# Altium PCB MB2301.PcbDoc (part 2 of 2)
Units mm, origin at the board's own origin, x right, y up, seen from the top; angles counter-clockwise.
Board outline 43 x 51.45 mm, 4 copper layers (Top Layer, Internal 1, Internal 2, Bottom Layer), stack 1.565 mm thick; 103 components, 91 nets, 383 pads, 756 vias.
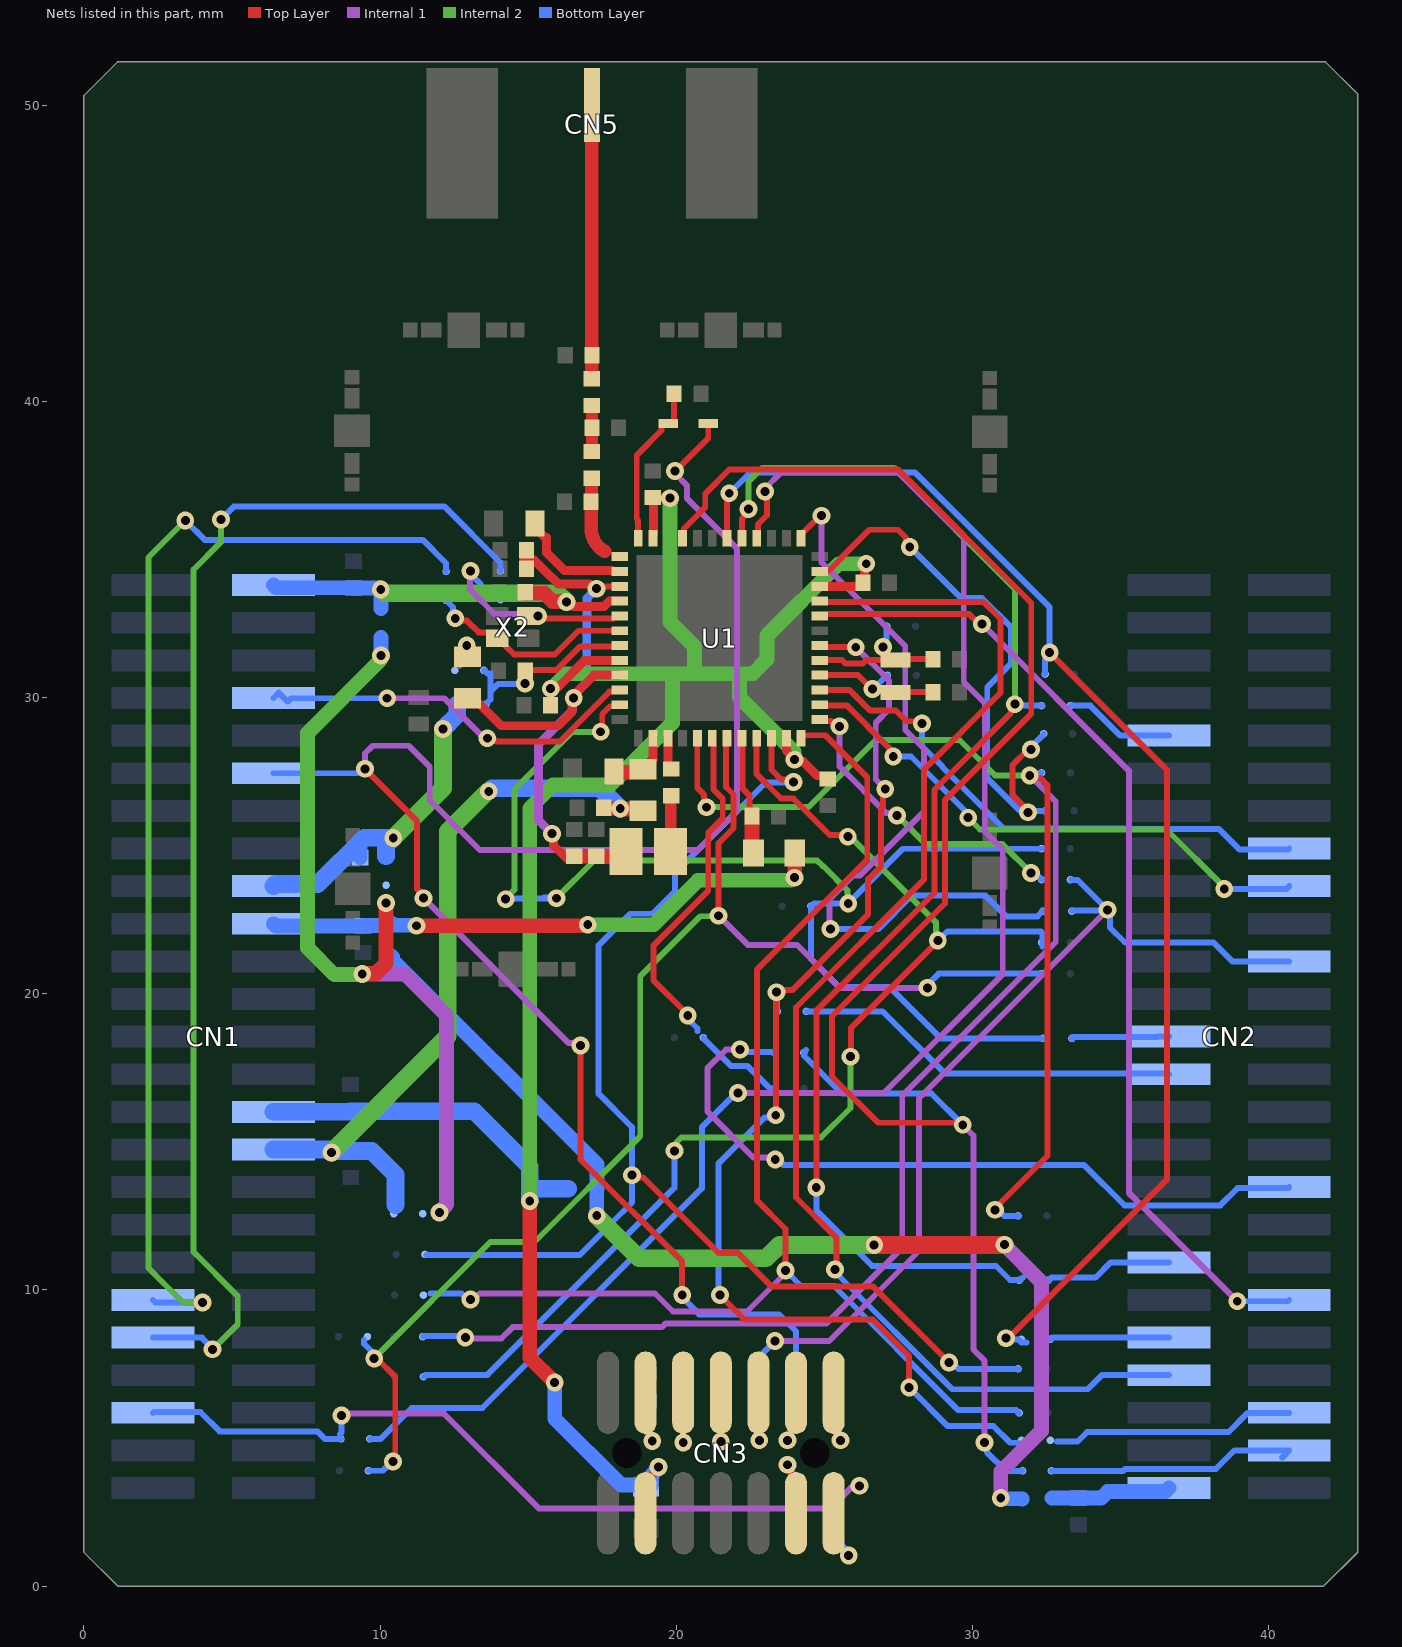
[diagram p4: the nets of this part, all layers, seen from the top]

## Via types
v1: diameter 0.6, hole 0.3, Top Layer to Bottom Layer, tented both sides, 756 vias

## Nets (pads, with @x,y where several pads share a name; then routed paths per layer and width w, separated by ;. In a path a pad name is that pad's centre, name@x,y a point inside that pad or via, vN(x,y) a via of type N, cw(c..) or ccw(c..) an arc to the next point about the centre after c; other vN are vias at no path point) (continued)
GPIO34: CN2.41 SB19.2 | length 4
  Bottom Layer w0.2: SB19.2@32.622,8.336 32.634,8.336 32.691,8.393 CN2.41@36.625,8.393
GPIO35: CN2.16 U1.15 | length 18.6
  Top Layer w0.2: U1.15@24.836,30.253 24.841,30.249 25.848,30.249 26.541,29.555 27.411,29.555 27.769,29.197 28.214,29.197 v1(28.291,29.121)
  Bottom Layer w0.2: v1(28.291,29.121) 28.291,28.364 28.975,27.68 28.975,27.655 31.057,25.573 35.106,25.573 35.124,25.555 38.323,25.555 39.002,24.875 40.661,24.875 CN2.16@40.689,24.903
GPIO36: CN2.18 U1.14 | length 18.7
  Top Layer w0.2: U1.14@24.836,29.753 24.853,29.737 25.746,29.737 27.174,28.308 27.174,28.262 27.321,28.115 v1(27.321,28.007)
  Internal 2 w0.2: v1(29.85,25.944) 30.249,25.545 36.543,25.545 38.495,23.593 v1(38.495,23.539)
  Bottom Layer w0.2: v1(27.321,28.007) 27.918,28.007 29.773,26.152 29.773,26.021 v1(29.85,25.944) ; v1(38.495,23.539) 40.595,23.539 CN2.18@40.689,23.633
GPIO37: CN1.45 R9.1 SB26.1 | length 27.6
  Internal 1 w0.2: v1(8.7,5.763) 8.762,5.825 12.158,5.825 15.354,2.629 25.199,2.629 25.883,3.313 26.104,3.313 v1(26.18,3.39)
  Bottom Layer w0.2: CN1.45@2.335,5.853 2.365,5.883 3.929,5.883 4.583,5.23 7.879,5.23 8.135,4.973 SB26.1@8.676,4.973 ; 8.645,5.13 8.7,5.185 v1(8.7,5.763) ; R9.1@25.3,2.825 25.395,2.825 25.96,3.39 v1(26.18,3.39)
GPIO38: CN2.22 R5.2 SB11.1 SB33.1 | length 31.6
  Internal 1 w0.2: v1(23.325,8.275) 25.15,8.275 28.19,11.315 28.19,16.468 v1(34.555,22.833)
  Bottom Layer w0.2: R5.2@22.77,7.176 22.814,7.219 22.814,7.763 v1(23.325,8.275) ; SB11.1@33.325,23.85 33.329,23.846 33.542,23.846 v1(34.555,22.833) ; SB33.1@33.35,22.8 33.36,22.81 v1@34.432,22.81 ; v1@34.432,22.833 v1(34.555,22.833) ; CN2.22@40.689,21.093 38.769,21.093 38.138,21.725 35.16,21.725 35.141,21.745 35.124,21.745 34.632,22.237 34.632,22.757 v1(34.555,22.833)
GPIO39: CN2.25 SB28.1 | length 3.3
  Bottom Layer w0.2: SB28.1@33.35,18.495 33.342,18.503 33.338,18.503 33.35,18.515 33.362,18.503 33.371,18.503 33.41,18.543 36.223,18.543 36.233,18.553 CN2.25@36.625,18.553
GPIO41: CN2.48 SB31.2 | length 8.7
  Bottom Layer w0.2: SB31.2@32.659,3.893 35.079,3.893 35.145,3.96 38.2,3.96 38.21,3.96 38.833,4.583 CN2.48@40.689,4.583 CN2.48@40.447,4.341
GPIO42: CN2.27 SB43.2 | length 13.1
  Bottom Layer w0.2: SB43.2@24.389,19.402 26.965,19.402 29.056,17.311 36.597,17.311 CN2.27@36.625,17.283
GPIO45: CN2.9 SB24.1 | length 3.7
  Bottom Layer w0.2: SB24.1@33.313,29.725 33.975,29.725 34.987,28.713 CN2.9@36.625,28.713
GPIO46: CN2.34 SB32.2 | length 25.3
  Internal 1 w0.2: v1(22.151,18.114) 21.674,18.114 21.044,17.483 21.044,16.028 22.597,14.475 23.262,14.475 v1(23.337,14.4)
  Bottom Layer w0.2: v1(22.151,18.114) 22.227,18.037 22.465,18.037 22.468,18.035 23.26,18.035 23.276,18.018 23.315,18.018 SB32.2@23.325,18.008 ; v1(23.337,14.4) 23.445,14.4 23.62,14.225 33.754,14.225 35.124,12.855 38.362,12.855 38.947,13.44 40.656,13.44 CN2.34@40.689,13.473
GPIO49: CN2.37 SB29.1 | length 4.3
  Bottom Layer w0.2: SB29.1@32.563,10.325 32.577,10.325 32.667,10.415 34.148,10.415 34.666,10.933 CN2.37@36.625,10.933
GPIO51: CN2.40 U1.20 | length 33.8
  Top Layer w0.2: U1.20@24.836,32.753 24.886,32.803 25.12,32.803 25.128,32.811 29.886,32.811 30.215,32.482 v1(30.32,32.482)
  Internal 1 w0.2: v1(30.32,32.482) 35.275,27.528 35.275,13.278 38.904,9.649 v1@38.921,9.649
  Bottom Layer w0.2: v1(38.934,9.619) 40.645,9.619 CN2.40@40.689,9.663
GPIO54: CN2.43 U1.21 | length 44.9
  Top Layer w0.2: U1.21@24.836,33.253 24.863,33.227 30.361,33.227 30.94,32.647 30.94,30.155 28.363,27.578 28.363,23.86 24.04,19.537 24.04,13.122 25.398,11.764 25.398,10.732 v1(25.356,10.691)
  Bottom Layer w0.2: v1(25.356,10.691) 25.356,10.607 29.313,6.65 33.89,6.65 34.363,7.123 CN2.43@36.625,7.123
GPIO55: CN1.8 U1.46 | length 13.3
  Top Layer w0.2: v1(13.619,28.625) 13.695,28.548 13.902,28.548 13.936,28.515 16.058,28.515 17.747,30.203 18.036,30.203 U1.46@18.086,30.253
  Internal 1 w0.2: v1(10.238,29.975) 12.161,29.975 13.511,28.625 v1(13.619,28.625)
  Bottom Layer w0.2: CN1.8@6.399,29.983 6.578,30.162 6.882,29.857 7,29.975 v1(10.238,29.975)
GPIO56: CN2.46 SB34.2 | length 8.2
  Bottom Layer w0.2: 32.849,4.885 33.543,4.885 33.86,5.202 38.638,5.202 39.29,5.853 CN2.46@40.689,5.853
NetC6_1: C6.1 L4.1 U1.2 | length 2.3
  Top Layer w0.3: L4.1@18.875,27.575 18.975,27.575 19.175,27.775 19.175,27.85 19.211,27.886 U1.2@19.211,28.628
  Top Layer w0.5: C6.1@17.9,27.5 17.95,27.45 17.97,27.47 18.258,27.47 18.263,27.475 18.775,27.475 L4.1@18.875,27.575
NetC7_2: C7.2 D1.1 U1.36 | length 5.6
  Top Layer w0.2: U1.36@18.711,35.378 18.711,35.968 18.661,36.018 18.661,38.18 19.5,39.019 19.5,39.194 19.55,39.244 19.875,39.244 19.925,39.294 C7.2@19.925,40.25
NetC8_1: C8.1 SB38.1 U1.16 X1.2 | length 4.8
  Top Layer w0.2: U1.16@24.836,30.753 26.132,30.753 26.6,30.285 v1(26.62,30.285) ; v1@26.61,30.275 26.66,30.225 27.337,30.225 X1.2@27.398,30.165 ; X1.2@27.398,30.1 X1.2@27.5,30.1 ; X1.2@27.5,30.18 C8.1@28.66,30.18
  Bottom Layer w0.2: v1(26.62,30.285) 26.645,30.285 27.11,30.75 SB38.1@27.125,30.75
NetC9_2: C9.2 SB37.1 U1.17 X1.1 | length 5.3
  Top Layer w0.2: U1.17@24.836,31.253 24.842,31.259 25.592,31.259 25.703,31.148 26.295,31.148 26.406,31.259 X1.1@27.231,31.259 ; v1(26.974,31.702) 26.998,31.679 26.998,31.415 27.153,31.259 X1.1@27.231,31.259 ; C9.2@28.663,31.295 27.428,31.295 27.392,31.259 X1.1@27.231,31.259
  Bottom Layer w0.2: v1(26.974,31.702) 26.974,31.811 27.098,31.935 SB37.1@27.098,32.407
NetC11_2: C11.2 U1.38 | length 3.9
  Top Layer w0.3: C11.2@15.225,35.875 15.225,35.75 15.581,35.394 15.619,35.394 15.619,34.89 16.219,34.29 17.836,34.29 17.873,34.253 U1.38@18.086,34.253
NetC12_1: C12.1 L1.1 U1.37 | length 2.6
  Top Layer w0.45: L1.1@17.15,37.4 17.15,37.385 17.135,37.37 17.135,36.619 C12.1@17.121,36.605 17.121,35.722 ccw(c18.033,35.722) 17.577,34.932
NetC13_2: C13.2 L1.2 L2.1 | length 1.6
  Top Layer w0.4: L2.1@17.145,39.858 17.147,39.856 17.147,39.102 C13.2@17.15,39.1 L1.2@17.15,38.3
NetC14_1: C14.1 CN5.1 L2.2 | length 9.2
  Top Layer w0.45: L2.2@17.145,40.758 17.147,40.761 17.147,41.548 C14.1@17.15,41.55 17.145,41.555 17.145,49.98 17.145,49.995 CN5.1@17.15,50
NetC15_1: C15.1 SB6.2 SB41.1 U1.43 | length 6.6
  Top Layer w0.2: v1(14.891,30.475) 14.896,30.479 14.896,30.899 14.922,30.925 15.95,30.925 16.75,31.725 18.058,31.725 U1.43@18.086,31.753
  Bottom Layer w0.2: SB41.1@13.501,30.917 13.515,30.917 13.615,30.817 13.72,30.817 13.72,30.195 ; SB6.2@13.575,29.775 13.575,29.785 13.72,29.93 13.72,30.195 ; v1(14.891,30.475) 14.878,30.462 13.987,30.462 13.72,30.195
NetC20_2: C20.2 L3.2 U1.8 | length 4
  Top Layer w0.2: U1.8@22.211,28.628 22.239,28.6 22.239,26.915 22.472,26.682 22.472,26.078 C20.2@22.55,26
  Top Layer w0.5: C20.2@22.55,26 22.555,25.995 22.555,24.795 L3.2@22.6,24.75
NetC23_2: C23.2 C24.1 C25.1 C26.1 L6.2 L7.1 U1.39 U1.45 | length 23.4
  Top Layer w0.2: C26.1@14.942,34.351 14.81,34.482 14.81,34.665 ; C24.1@14.942,34.976 14.81,34.844 14.81,34.665 ; 15.168,34.665 14.81,34.665 ; v1(17.308,33.673) 17.416,33.673 17.497,33.753 U1.39@18.086,33.753
  Top Layer w0.3: L7.1@12.95,29.975 13.15,29.775 13.358,29.775 14.086,29.046 16.01,29.046 16.483,29.519 16.483,29.93 v1(16.533,29.98) ; 15.168,34.665 15.763,34.07 15.772,34.07 16.005,33.837 17.063,33.837 17.227,33.673 v1(17.308,33.673) ; v1(15.801,25.404) 15.858,25.346 15.858,25.004 16.308,24.555 16.445,24.555 16.532,24.642 C23.2@16.55,24.642 ; v1@16.489,30.024 17.218,30.753 U1.45@18.086,30.753
  Top Layer w0.5: C23.2@16.55,24.637 16.555,24.642 18.142,24.642 L6.2@18.3,24.8
  Internal 1 w0.3: v1(15.801,25.404) 15.345,25.86 15.345,28.42 16.495,29.57 16.495,29.942 v1(16.533,29.98)
  Bottom Layer w0.3: v1(16.533,29.98) 16.533,30.068 16.975,30.51 16.975,32.773 16.977,32.775 16.977,33.342 v1(17.308,33.673)
NetCN3_4: CN3.4 R2.1 | length 3.2
  Top Layer w0.2: CN3.4@18.96,6.532 19.061,6.431 19.061,5.13 19.184,5.007 v1(19.184,4.902)
  Bottom Layer w0.2: R2.1@18.975,6.258 18.944,6.227 18.944,5.248 19.184,5.007 v1(19.184,4.902)
NetCN3_6: CN3.6 R3.1 | length 3.1
  Top Layer w0.2: v1(20.23,4.85) CN3.6@20.23,6.532
  Bottom Layer w0.2: R3.1@20.211,6.276 20.23,6.257 v1(20.23,4.85)
NetCN3_8: CN3.8 R4.1 | length 3
  Top Layer w0.2: v1(21.5,4.885) CN3.8@21.5,6.532
  Bottom Layer w0.2: R4.1@21.49,6.258 21.5,6.248 v1(21.5,4.885)
NetCN3_10: CN3.10 R5.1 | length 3
  Top Layer w0.2: CN3.10@22.77,6.532 22.785,6.517 22.785,4.94 v1(22.8,4.925)
  Bottom Layer w0.2: R5.1@22.77,6.276 22.8,6.246 v1(22.8,4.925)
NetCN3_11: CN3.11 R6.2 | length 3.1
  Top Layer w0.2: v1(23.755,4.1) 23.83,4.025 23.83,3.841 23.939,3.732 23.939,2.564 CN3.11@24.04,2.462
  Bottom Layer w0.2: v1(23.755,4.1) 23.755,3.994 24.018,3.731 R6.2@24.018,2.875
NetCN3_12: CN3.12 R7.1 | length 3.2
  Top Layer w0.2: v1(23.755,4.925) 23.83,5 23.83,5.153 24.04,5.364 CN3.12@24.04,6.532
  Bottom Layer w0.2: v1(23.755,4.925) 23.83,5 23.83,5.438 24.037,5.645 24.037,6.255 R7.1@24.04,6.258
NetCN3_13: CN3.13 R9.2 | length 2.8
  Top Layer w0.2: CN3.13@25.31,2.462 25.31,1.491 25.762,1.039 v1(25.815,1.039)
  Bottom Layer w0.2: R9.2@25.3,1.925 25.395,1.925 25.545,1.775 25.545,1.415 25.815,1.144 v1(25.815,1.039)
NetCN3_14: CN3.14 R8.1 | length 3.1
  Top Layer w0.2: CN3.14@25.31,6.532 25.411,6.431 25.411,5.157 25.538,5.031 v1(25.538,4.925)
  Bottom Layer w0.2: R8.1@25.31,6.258 25.31,5.259 25.538,5.031 v1(25.538,4.925)
NetL5_1: L5.1 U1.3 | length 1
  Top Layer w0.2: L5.1@19.674,27.596 L5.1@19.711,27.633
  Top Layer w0.3: L5.1@19.711,27.633 U1.3@19.711,28.628
NetL5_2: L5.2 L6.1 | length 1.9
  Top Layer w0.4: L6.1@19.8,24.8 19.812,24.812 19.812,26.671 L5.2@19.824,26.683
NetL7_2: L7.2 SB41.2 | length 1.2
  Top Layer w0.2: v1(12.923,31.757) 12.923,31.402 L7.2@12.95,31.375
  Bottom Layer w0.2: 12.702,31.075 12.702,31.44 12.923,31.661 v1(12.923,31.757)
NetSB1_1: SB1.1 SB2.1 SB3.1 SB4.1 SB5.1 SB36.1 | length 64.2
  Top Layer w0.5: v1(9.397,20.663) 9.416,20.682 9.86,20.682 10.2,21.022 v1(10.2,23.064)
  Top Layer w0.6: v1(26.676,11.519) 31.069,11.519 v1(31.079,11.529)
  Internal 1 w0.5: v1(9.397,20.663) 10.848,20.663 12.24,19.271 12.24,12.882 12.001,12.643 v1(12.001,12.616) ; v1(30.95,2.975) 30.95,3.869 32.325,5.244 32.325,10.258 v1@31.079,11.505
  Internal 2 w0.5: v1@9.378,20.645 8.455,20.645 7.546,21.554 7.546,28.799 10.006,31.258 10.006,31.396 v1(10.025,31.415)
  Internal 2 w0.6: v1(17.312,12.508) 17.312,12.494 18.739,11.067 23.028,11.067 23.479,11.519 v1(26.676,11.519)
  Bottom Layer w0.5: v1(9.397,20.663) 9.416,20.682 9.86,20.682 10.136,20.959 ; v1(10.025,31.415) SB2.1@10.025,32.025 ; 10.413,21.235 10.413,21.154 17.32,14.247 SB4.1@17.32,13.419 17.31,13.41 17.31,12.554 17.312,12.552 v1(17.312,12.508) ; v1(30.95,2.975) 30.969,2.956 31.664,2.956 SB36.1@31.675,2.945
NetSB7_2: SB7.2 SB8.2 U1.10 | length 43.8
  Top Layer w0.2: v1(18.5,13.875) 18.575,13.8 18.874,13.8 21.42,11.255 22.075,11.255 23.219,10.111 26.647,10.111 v1@29.201,7.558 ; U1.10@23.211,28.628 23.211,27.56 23.543,27.228 23.872,27.228 v1(23.949,27.152)
  Bottom Layer w0.2: SB8.2@11.563,11.175 16.728,11.175 17.511,11.958 17.54,11.958 17.862,12.28 17.862,12.31 18.5,12.947 v1(18.5,13.875) 18.5,15.496 17.375,16.621 17.375,21.635 18.441,22.701 19.204,22.701 19.946,23.444 19.946,24.062 23.017,27.133 23.93,27.133 v1(23.949,27.152) ; v1(29.201,7.548) 29.309,7.548 29.518,7.339 SB7.2@31.55,7.339
NetSB9_2: SB9.2 SB12.2 SB21.2 U1.5 | length 67.9
  Top Layer w0.2: U1.5@20.711,28.628 20.704,28.621 20.704,26.951 20.939,26.716 20.939,26.373 v1(21.016,26.297) ; v1(30.756,12.705) 30.756,12.759 32.53,14.533 32.53,27.048 32.288,27.29 32.005,27.29 v1(31.93,27.365)
  Internal 1 w0.2: v1(12.875,8.393) 12.908,8.36 14.091,8.36 14.476,8.746 19.513,8.746 19.639,8.872 25.072,8.872 27.625,11.425 27.625,16.564 32.805,21.744 32.805,26.49 v1(31.93,27.365)
  Internal 2 w0.2: v1(21.016,26.297) 24.459,26.297 26.729,28.566 29.558,28.566 30.759,27.365 v1(31.93,27.365)
  Bottom Layer w0.2: SB9.2@11.439,8.425 11.45,8.425 11.467,8.442 12.826,8.442 v1(12.875,8.393) ; v1(30.756,12.705) 30.862,12.705 31.067,12.5 SB12.2@31.55,12.5 ; v1(31.93,27.365) 32.005,27.439 32.295,27.439 32.314,27.458 SB21.2@32.326,27.458
NetSB10_1: SB10.1 SB13.1 U1.23 | length 19.7
  Top Layer w0.2: U1.23@24.836,34.253 24.881,34.298 25.167,34.298 25.552,34.683 25.552,34.7 26.513,35.661 27.481,35.661 27.752,35.391 27.752,35.073 v1@27.775,35.05 ; v1(31.865,26.123) 31.865,26.189 31.35,26.703 31.35,27.725 31.87,28.245 v1(31.971,28.245)
  Bottom Layer w0.2: v1(27.876,35.077) 27.891,35.077 29.614,33.354 30.318,33.354 31.288,32.385 31.288,31.143 30.493,30.348 30.493,27.276 31.572,26.197 31.79,26.197 v1(31.865,26.123) ; v1@31.876,26.111 31.929,26.165 32.429,26.165 SB10.1@32.438,26.173 ; v1(31.971,28.245) 31.971,28.333 32.401,28.763 SB13.1@32.401,28.775
NetSB11_2: SB11.2 U1.13 | length 10.5
  Top Layer w0.2: U1.13@24.836,29.253 24.886,29.203 25.221,29.203 25.398,29.026 v1(25.506,29.026)
  Internal 1 w0.2: v1(25.506,29.026) 25.506,27.675 27.084,26.097 27.373,26.097 v1(27.45,26.021)
  Internal 2 w0.2: v1(27.45,26.021) 28.423,25.048 31.002,25.048 v1(31.975,24.075)
  Bottom Layer w0.2: v1(31.975,24.075) 32.052,23.998 32.187,23.998 32.335,23.85 SB11.2@32.35,23.85
NetSB14_2: SB14.2 SB17.2 U1.9 | length 40
  Top Layer w0.2: U1.9@22.711,28.628 22.711,27.411 23.533,26.59 23.949,26.59 25.187,25.352 25.736,25.352 v1(25.787,25.301) ; v1(25.875,17.875) 25.887,17.887 25.887,18.837 28.825,21.775 v1(28.825,21.8)
  Internal 2 w0.2: v1(19.932,14.697) 20.007,14.772 20.007,14.982 20.175,15.15 24.884,15.15 25.875,16.141 v1(25.875,17.875) ; v1(25.787,25.301) 25.874,25.301 28.76,22.415 28.76,21.865 v1(28.825,21.8)
  Bottom Layer w0.2: SB14.2@11.463,7.076 11.478,7.076 11.535,7.134 13.619,7.134 19.932,13.447 v1(19.932,14.697) ; v1@28.837,21.787 29.149,22.099 32.305,22.099 32.35,22.054 32.35,21.6
NetSB16_2: SB16.2 SB18.2 U1.12 | length 44.4
  Top Layer w0.2: v1(23.682,10.661) 23.682,12.06 22.717,13.025 22.717,20.805 26.443,24.531 26.443,27.312 25.03,28.725 24.256,28.725 24.211,28.68 U1.12@24.211,28.628
  Internal 1 w0.2: v1(13.05,9.675) 13.158,9.675 13.364,9.881 19.28,9.881 19.885,9.275 22.382,9.275 23.682,10.575 v1(23.682,10.661)
  Bottom Layer w0.2: 11.705,9.875 12.744,9.875 12.944,9.675 v1(13.05,9.675) ; v1(23.682,10.661) 24.208,10.136 25.319,10.136 29.511,5.943 31.47,5.943 31.56,5.853 SB18.2@31.572,5.853
NetSB19_1: SB19.1 SB22.1 U1.30 | length 44.7
  Top Layer w0.2: U1.30@21.711,35.378 21.711,36.822 v1(21.784,36.895) ; v1(31.129,8.374) 31.199,8.374 36.565,13.74 36.565,27.55 v1(32.6,31.515)
  Bottom Layer w0.2: v1@21.795,36.895 22.5,37.6 28.049,37.6 32.6,33.049 v1(32.6,31.515) 32.6,31.424 32.439,31.263 SB22.1@32.439,30.79 ; v1(31.129,8.374) 31.17,8.332 31.543,8.332 31.645,8.23 31.823,8.23
NetSB23_2: SB23.2 SB28.2 SB30.2 U1.47 | length 41.6
  Top Layer w0.2: v1(17.445,28.842) 17.496,28.893 17.496,29.442 17.758,29.703 18.036,29.703 U1.47@18.086,29.753
  Internal 2 w0.2: v1(14.238,23.192) 14.238,23.216 14.532,23.51 14.532,26.881 16.492,28.842 v1(17.445,28.842) ; v1(15.95,23.223) 17.219,24.492 24.755,24.492 24.937,24.31 24.953,24.31 25.782,23.481 25.782,23.068 v1(25.8,23.05)
  Bottom Layer w0.2: v1(14.238,23.192) 14.253,23.208 15.935,23.208 v1(15.95,23.223) 15.925,23.248 15.526,23.248 ; SB23.2@32.348,24.894 27.644,24.894 v1(25.8,23.05) 24.648,23.05 24.558,22.96 SB30.2@24.543,22.96 24.543,21.175 25.485,20.233 27.191,20.233 28.929,18.495 SB28.2@32.375,18.495
NetSB24_2: SB24.2 SB29.2 U1.29 | length 45.6
  Top Layer w0.2: U1.29@22.211,35.378 22.211,36.03 22.436,36.255 v1(22.436,36.361) ; v1(24.723,13.46) 24.723,19.423 28.713,23.413 28.713,26.89 31.287,29.464 31.287,29.529 31.425,29.667 v1(31.425,29.775)
  Internal 2 w0.2: v1(22.436,36.361) 22.436,37.283 22.903,37.75 27.35,37.75 31.425,33.675 v1(31.425,29.775)
  Bottom Layer w0.2: v1(24.723,13.46) 24.723,12.694 26.61,10.807 30.786,10.807 31.259,10.335 31.578,10.335 31.588,10.325 31.602,10.325 31.702,10.425 ; v1(31.425,29.775) 31.467,29.733 32.329,29.733 SB24.2@32.338,29.725
NetSB26_2: SB26.2 U1.28 | length 54
  Top Layer w0.2: U1.28@22.711,35.378 22.756,35.423 22.756,35.847 23.053,36.144 23.053,36.894 v1(22.991,36.955)
  Internal 1 w0.2: v1(22.075,16.654) 27.009,16.654 31.017,20.661 31.017,24.868 30.41,25.475 30.41,29.812 29.7,30.521 29.7,35.4 27.51,37.59 23.528,37.59 22.991,37.053 v1(22.991,36.955)
  Bottom Layer w0.2: SB26.2@9.651,4.973 10.018,4.973 11.063,6.018 13.449,6.018 20.861,13.43 20.861,15.494 22.021,16.654 v1(22.075,16.654)
NetSB31_1: SB31.1 SB32.1 U1.33 | length 58.3
  Top Layer w0.2: U1.33@20.211,35.378 20.261,35.428 20.261,35.707 20.458,35.903 20.459,35.903 20.975,36.419 20.975,36.88 21.795,37.7 27.47,37.7 31.98,33.19 31.98,29.448 29.063,26.531 29.063,23.048 25.254,19.239 25.254,17.206 26.816,15.645 29.595,15.645 v1(29.665,15.575)
  Internal 1 w0.2: v1(29.665,15.575) 30.025,15.215 30.025,7.992 30.404,7.613 v1(30.404,4.85)
  Bottom Layer w0.2: SB32.1@24.375,18.097 24.3,18.022 SB32.1@24.3,18.008 24.31,17.997 24.31,17.907 25.584,16.634 28.606,16.634 v1(29.665,15.575) ; v1(30.404,4.85) 30.478,4.775 30.478,4.528 31.113,3.893 SB31.1@31.684,3.893
NetSB33_2: SB33.2 U1.25 | length 25.9
  Top Layer w0.2: U1.25@24.211,35.378 24.211,35.503 24.846,36.138 v1(24.9,36.138)
  Internal 1 w0.2: v1(24.9,36.138) 24.9,34.561 27.725,31.736 27.725,28.902 28.363,28.264 28.363,26.156 26.202,23.994 25.966,23.994 25.167,23.195 25.167,22.222 v1(25.2,22.188)
  Bottom Layer w0.2: v1(25.2,22.188) 26.829,22.188 27.955,23.315 30.432,23.315 31.133,22.614 32.189,22.614 SB33.2@32.375,22.8
NetSB34_1: SB34.1 SB43.1 U1.18 | length 40.1
  Top Layer w0.2: v1(21.471,9.83) 21.471,9.827 22.302,8.996 26.629,8.996 27.858,7.767 v1(27.858,6.708) ; v1(23.353,15.9) 23.364,15.911 23.364,20.042 23.452,20.129 23.926,20.129 26.475,22.679 26.475,23.866 26.9,24.291 26.9,26.248 26.973,26.322 26.973,26.832 v1(27.05,26.909) ; U1.18@24.836,31.753 24.884,31.706 v1@26.048,31.706
  Internal 1 w0.2: v1(26.056,31.698) 27.175,30.579 27.175,29.593 26.729,29.146 26.729,27.23 v1(27.05,26.909)
  Bottom Layer w0.2: v1(21.471,9.83) 21.425,9.876 21.425,14.274 22.978,15.827 23.279,15.827 v1(23.353,15.9) ; v1(23.375,20.053) 23.401,20.027 23.401,19.415 SB43.1@23.414,19.402 ; v1(27.858,6.708) 29.161,5.405 30.706,5.405 31.267,4.844 31.541,4.844
NetSB39_1: SB39.1 U1.42 X2.1 | length 7.2
  Top Layer w0.2: v1(12.535,32.672) 12.612,32.596 12.929,32.596 13.325,32.2 13.75,32.2 X2.1@13.95,32 14.025,32 14.225,31.8 14.225,31.746 14.521,31.45 15.891,31.45 16.694,32.253 U1.42@18.086,32.253
  Bottom Layer w0.2: SB39.1@12.225,33.282 12.461,33.046 12.461,32.747 v1(12.535,32.672)
NetSB40_1: SB40.1 U1.41 X2.3 | length 7.6
  Top Layer w0.2: v1(15.324,32.75) 15.401,32.673 15.637,32.673 15.641,32.669 17.877,32.669 17.911,32.703 18.036,32.703 U1.41@18.086,32.753
  Internal 1 w0.2: v1(13.051,34.27) 13.035,34.254 13.035,33.642 13.862,32.816 15.258,32.816 v1(15.324,32.75)
  Bottom Layer w0.2: v1(13.051,34.27) 13.051,34.161 13.41,33.802 13.41,33.737 13.682,33.465 13.883,33.465 14.048,33.3 SB40.1@14.063,33.3
NetSB44_2: SB44.2 SB45.2 SB48.2 U1.7 | length 45.1
  Top Layer w0.2: v1(9.798,7.689) 9.893,7.689 10.509,7.073 10.509,4.285 v1(10.434,4.21) ; v1(21.425,22.632) 21.426,25.088 21.927,25.59 21.927,26.725 21.674,26.978 21.674,28.591 U1.7@21.711,28.628
  Internal 1 w0.2: v1(21.425,22.632) 22.409,21.648 24.07,21.648 25.518,20.2 v1(28.475,20.2)
  Internal 2 w0.2: v1(9.798,7.689) 9.798,7.697 13.721,11.621 15.209,11.621 18.78,15.191 18.78,20.586 20.81,22.616 21.409,22.616 v1(21.425,22.632)
  Bottom Layer w0.2: 9.457,8.314 9.457,8.18 9.798,7.839 v1(9.798,7.689) ; SB44.2@9.604,3.898 10.094,3.898 10.406,4.21 v1(10.434,4.21) ; v1(28.475,20.2) 28.475,20.3 28.853,20.678 SB48.2@32.348,20.678
NetSB46_2: SB46.2 SB47.2 U1.6 | length 14.8
  Top Layer w0.2: v1(20.384,19.265) 20.384,19.297 19.221,20.461 19.221,21.62 21.076,23.475 21.076,25.435 21.566,25.925 21.566,26.584 21.25,26.9 21.25,28.59 U1.6@21.211,28.628
  Bottom Layer w0.2: v1(20.384,19.265) 20.384,19.157 20.713,18.829 20.713,18.735 ; SB46.2@20.907,18.52 20.907,18.495 21.838,17.564 22.398,17.564 23.152,16.809 SB47.2@23.336,16.809
NRST: CN1.12 D1.2 R7.2 | length 61.7
  Top Layer w0.2: v1(9.485,27.591) 11.24,25.837 11.24,23.543 11.46,23.322 v1(11.46,23.226) ; v1(16.766,18.257) 16.766,14.397 20.196,10.967 v1(20.196,9.83) ; v1(19.951,37.65) 19.974,37.65 21.075,38.751 D1.2@21.075,39.244
  Internal 1 w0.2: v1(9.485,27.591) 9.485,28.109 9.747,28.37 10.97,28.37 11.675,27.665 11.675,26.542 13.365,24.851 20.729,24.851 22.053,26.175 22.053,35.021 20.361,36.712 20.361,37.149 19.951,37.56 v1(19.951,37.65) ; v1(11.46,23.226) 11.472,23.226 16.365,18.333 16.689,18.333 v1(16.766,18.257)
  Bottom Layer w0.2: CN1.12@6.399,27.443 9.229,27.443 9.377,27.591 v1(9.485,27.591) ; v1(20.196,9.83) 20.196,9.75 20.769,9.177 23.466,9.177 24.04,8.603 R7.2@24.04,7.158
OSC_IN: CN1.39 SB39.2 | length 39.4
  Internal 2 w0.2: v1(3.425,35.975) 2.175,34.725 2.175,10.743 3.343,9.575 v1(4,9.575)
  Bottom Layer w0.2: CN1.39@2.335,9.663 2.423,9.575 v1(4,9.575) ; v1(3.425,35.975) 4.08,35.32 11.435,35.32 12.225,34.53 SB39.2@12.225,34.257
OSC_OUT: CN1.41 SB40.2 | length 42.3
  Internal 2 w0.2: v1(4.345,7.996) 5.193,8.844 5.193,9.793 3.7,11.286 3.7,34.315 4.624,35.24 v1(4.624,36.008)
  Bottom Layer w0.2: CN1.41@2.335,8.393 3.982,8.393 4.354,8.022 4.354,8.005 v1(4.345,7.996) ; v1(4.624,36.008) 5.057,36.441 5.181,36.441 5.193,36.452 12.162,36.452 14.063,34.552 SB40.2@14.063,34.275
VDD1: C2.2 C10.1 CN1.2 SB2.2 U1.40 | length 14.3
  Top Layer w0.2: U1.40@18.075,33.242 U1.40@18.086,33.253 U1.40@18.081,33.248
  Top Layer w0.3: v1(16.294,33.223) 16.375,33.223 16.525,33.073 17.557,33.073 17.687,33.203 17.692,33.203 17.742,33.253 U1.40@18.081,33.253
  Top Layer w0.5: C10.1@14.9,33.55 14.9,33.525 14.905,33.52 15.544,33.52 15.822,33.242 16.275,33.242 v1(16.294,33.223)
  Internal 2 w0.6: v1(10.022,33.641) 10.143,33.52 15.997,33.52 v1(16.294,33.223)
  Bottom Layer w0.5: CN1.2@6.399,33.793 6.487,33.705 9.095,33.705 9.105,33.695 9.94,33.695 9.995,33.641 v1(10.022,33.641) ; SB2.2@10.025,33 v1@10.025,33.637
VDD3: C3.2 CN1.18 SB3.2 SB6.1 | length 11.6
  Internal 2 w0.6: v1(10.444,25.26) 12.119,26.935 v1(12.119,28.933)
  Bottom Layer w0.5: C3.2@9.329,24.592 9.329,25.135
  Bottom Layer w0.6: CN1.18@6.399,23.633 6.468,23.702 7.896,23.702 9.462,25.268 ; 9.329,25.135 9.462,25.268 ; SB3.2@10.2,24.638 10.2,25.016 v1(10.444,25.26) 10.436,25.268 9.462,25.268 ; v1(12.119,28.933) 12.6,29.414 SB6.1@12.6,29.775
VDD4: C4.2 C16.1 C17.1 C18.1 C19.1 C22.2 CN1.30 CN3.3 SB4.2 U1.11 U1.22 U1.35 U1.44 | length 79.5
  Top Layer w0.2: C19.1@15.75,29.745 15.753,29.748 15.753,30.295 v1(15.755,30.298)
  Top Layer w0.3: v1(15.755,30.298) 15.813,30.355 16.007,30.355 16.905,31.253 U1.44@18.086,31.253 ; CN3.3@18.96,2.462 18.96,3.534 19.4,3.974 v1(19.4,4.02) ; U1.35@19.211,35.378 19.211,35.458 19.228,35.475 19.228,36.753 19.241,36.74 19.77,36.74 v1(19.781,36.729) ; U1.11@23.711,28.628 23.711,28.202 23.985,27.928 v1(23.985,27.901) 24.042,27.843 24.271,27.843 24.757,27.357 25.006,27.357 C16.1@25.111,27.252 ; U1.22@24.836,33.753 26.019,33.753 26.036,33.77 26.195,33.77 26.355,33.93 26.355,34.458 v1(26.41,34.513)
  Top Layer w0.5: v1@15.051,12.973 15.051,7.716 v1(15.891,6.875)
  Internal 2 w0.2: v1(15.755,30.298) v1@15.802,30.298
  Internal 2 w0.5: v1(15.051,13) 15.051,26.26 15.839,27.048 17.778,27.048 19.87,29.141 19.87,30.802 ; v1@15.802,30.298 15.802,30.317 16.286,30.802 19.87,30.802 ; v1(19.781,36.729) 19.781,32.552 20.614,31.718 20.614,30.802 ; v1(23.985,27.901) 23.966,27.92 23.966,28.176 22.131,30.011 22.131,30.802 ; v1(26.41,34.513) 25.478,34.513 23.059,32.094 23.059,31.286 22.574,30.802 22.131,30.802 ; 19.87,30.802 20.614,30.802 ; 20.614,30.802 22.131,30.802
  Bottom Layer w0.5: v1(15.891,6.875) 15.891,5.658 18.129,3.42 18.905,3.42 C22.2@18.975,3.35 19.1,3.35 19.17,3.42 19.17,3.763 19.4,3.993 v1(19.4,4.02)
  Bottom Layer w0.6: CN1.30@6.399,16.013 8.978,16.013 C4.2@9.001,16.036 13.175,16.036 15.05,14.161 15.05,13.419 v1(15.051,13) ; 15.184,13.419 SB4.2@16.345,13.419
VDD5: C5.2 C21.1 CN1.32 L4.2 SB5.2 | length 26.1
  Top Layer w0.5: C21.1@17.55,26.275 17.55,26.268 17.555,26.263 v1@18.092,26.263 ; v1(18.104,26.25) v1@18.092,26.263 ; L4.2@18.875,26.175 18.819,26.231 18.123,26.231 v1@18.092,26.263
  Internal 2 w0.6: v1(8.355,14.642) 12.284,18.571 12.284,25.481 13.635,26.832 v1(13.665,26.832)
  Bottom Layer w0.6: CN1.32@6.399,14.743 8.355,14.743 v1(8.355,14.642) 8.402,14.689 C5.2@9.005,14.689 ; C5.2@9.018,14.692 9.719,14.692 10.521,13.89 10.521,12.866 ; v1(13.665,26.832) 13.768,26.935 17.419,26.935 v1(18.104,26.25)
VDD14: C27.2 CN2.49 SB36.2 | length 4.1
  Bottom Layer w0.5: SB36.2@32.681,2.975 C27.2@33.575,2.975 33.58,2.98 34.341,2.98 34.555,3.195 36.507,3.195 CN2.49@36.625,3.313
VDDA: C1.2 CN1.20 L3.1 SB1.2 | length 19.2
  Top Layer w0.5: v1(11.229,22.293) 16.942,22.293 16.98,22.331 v1(17.007,22.331) ; v1(23.992,23.918) 23.996,23.922 23.996,24.746 L3.1@24,24.75
  Internal 2 w0.5: v1@17.034,22.331 19.236,22.331 20.733,23.829 23.875,23.829 23.965,23.918 v1(23.992,23.918)
  Bottom Layer w0.5: CN1.20@6.399,22.363 6.474,22.288 9.417,22.288 9.427,22.298 10.348,22.298 SB1.2@10.413,22.364 10.464,22.312 11.21,22.312 v1(11.229,22.293)
pads on no net: CN1.3 CN1.4 CN1.5 CN1.10 CN1.11 CN1.16 CN1.19 CN1.21 CN1.23 CN1.27 CN1.43 CN1.48 CN1.50 CN2.1 CN2.3 CN2.4 CN2.5 CN2.6 CN2.17 CN2.19 CN2.24 CN2.28 CN2.30 CN2.31 CN2.33 CN2.36 CN2.47 CN3.1 CN3.2 CN3.9 CN3.NPTH1 CN3.NPTH2 U1.19 U1.31 U1.32 U1.48

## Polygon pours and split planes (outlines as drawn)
GND on Bottom Layer "Bottom Layer-GND" (solid, remove dead copper, pour order 7): -5.722,60.183 47.45,60.183 47.45,-6.633 -5.722,-6.633
GND on Internal 2 "Internal 2-GND" (solid, remove dead copper, pour order 11): -6.863,54.407 46.703,54.407 46.703,-2.025 -6.863,-2.025
GND on Internal 1 "GND_L02_P016" (solid, remove dead copper, pour order 16): 18.5,52.219 18.5,34.43 15.86,34.43 15.86,52.219 -1.639,52.219 -1.639,-2.225 44.069,-2.225 45.097,-0.949 45.097,-0.533 45.097,52.219
GND on Top Layer "Top Layer-GND" (solid, remove dead copper, pour order 9): -0.984,56.842 44.025,56.842 44.025,-1.8 -0.984,-1.8

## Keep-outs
Top Layer:
  rectangle: 16.907,40.223 17.392,40.384
  rectangle: 16.912,37.765 17.397,37.926
  rectangle: 18.61,29.16 24.299,34.848
Keep-Out Layer:
  lines w0.1: 43.001,1.145 43.001,39.986 43.001,50.374 41.925,51.45 1.127,51.45 0.001,50.324 0.001,1.143 1.139,0.005 41.852,0.005 42.505,0.652 43.002,1.145

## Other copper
Top Layer:
  region net NetC12_1: 17.699,35.121 18.079,34.903 18.361,34.903 18.361,34.603 17.811,34.603 17.498,34.721 17.489,34.724
  text "1" at 10.365,1.475 h0.81
Internal 1:
  text "2" at 10.91,1.475 h0.81
Internal 2:
  text "3" at 11.59,1.484 h0.81
Bottom Layer:
  text "4" at 12.616,1.475 h0.81
Multi-Layer:
  pour cut-out: 10.149,2.2 10.147,1.375 12.802,1.375 12.802,2.2

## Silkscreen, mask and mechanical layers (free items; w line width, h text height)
Top Overlay:
  lines w0.05: -0.591,0.005 1.139,0.005 ; 0.001,-0.496 0.001,1.143
  lines w0.1: 19.401,26.144 19.572,26.001 ; 19.551,26.322 19.408,26.152 20.14,26.152 ; 10.149,1.325 12.775,1.325 12.775,2.2 10.149,2.2 10.149,1.325
  lines w0.15: 9.048,20.826 30.548,20.826 30.548,42.326 9.048,42.326 9.048,20.826
  text "J" at 1.575,47.57 h7.62
  text "K" at 1.325,42.527 h7.62
  text "MB2301A" at 1.101,1.405 h2.5
Bottom Overlay:
  drawing of 200 lines, arcs and shapes, not listed
  text "Layer" at -15.37,133.178 h1.52
  text "Name" at -8.992,133.178 h1.52
  text "Material" at 3.342,133.178 h1.52
  text "Thickness" at 14.425,133.178 h1.52
  text "Constant" at 23.529,133.178 h1.52
  text "Board Layer Stack" at 31.955,133.178 h1.52
  text "Top Overlay" at -8.992,130.13 h1.52
  text "Top Solder" at -8.992,127.082 h1.52
  text "Solder Resist" at 3.342,127.082 h1.52
  text "0.018mm" at 14.425,127.082 h1.52
  text "4.2" at 23.529,127.082 h1.52
  text "1" at -15.37,124.034 h1.52
  text "Top Layer" at -8.992,124.034 h1.52
  text "0.041mm" at 14.425,124.034 h1.52
  text "Dielectric 1" at -8.992,120.986 h1.52
  text "FR-4" at 3.342,120.986 h1.52
  text "0.076mm" at 14.425,120.986 h1.52
  text "3.7" at 23.529,120.986 h1.52
  text "2" at -15.371,117.938 h1.52
  text "Internal 1" at -8.992,117.938 h1.52
  text "0.030mm" at 14.425,117.938 h1.52
  text "Dielectric 3" at -8.992,114.89 h1.52
  text "FR-4" at 3.342,114.89 h1.52
  text "1.270mm" at 14.425,114.89 h1.52
  text "4.5" at 23.529,114.89 h1.52
  text "3" at -15.37,111.842 h1.52
  text "Internal 2" at -8.992,111.842 h1.52
  text "0.030mm" at 14.425,111.842 h1.52
  text "Dielectric 2" at -8.992,108.794 h1.52
  text "FR-4" at 3.342,108.794 h1.52
  text "0.076mm" at 14.425,108.794 h1.52
  text "3.7" at 23.529,108.794 h1.52
  text "4" at -15.37,105.746 h1.52
  text "Bottom Layer" at -8.992,105.746 h1.52
  text "0.041mm" at 14.425,105.746 h1.52
  text "Bottom Solder" at -8.992,102.698 h1.52
  text "Solder Resist" at 3.342,102.698 h1.52
  text "0.018mm" at 14.425,102.698 h1.52
  text "4.2" at 23.529,102.698 h1.52
  text "Bottom Overlay" at -8.992,99.65 h1.52
  text "Total board thickness:" at -15.37,96.602 h1.52
  text "1.600mm" at 14.425,96.602 h1.52
  text "J" at 41.4,46.975 h7.62
  text "C" at 6.561,46.705 h7.62
  text "G" at 34.341,46.58 h7.62
  text "K" at 41.5,41.892 h7.62
  text "I" at 5.509,41.806 h7.62
  text "H" at 6.415,37.412 h7.62
  text "E" at 41.4,37.225 h7.62
Top Solder:
  lines w0.1: 9.015,36.629 9.025,36.629 ; 18.361,20.621 18.361,20.624
  lines w0.5: 8.992,41.562 8.992,42.625 15.431,42.625 ; 9.066,28.177 9.066,36.452 ; 10.725,20.65 11.982,20.658 ; 17.103,20.676 18.28,20.676 ; 23.992,42.568 30.912,42.568 30.912,41.491 ; 29.065,20.624 30.95,20.624 30.95,21.462 ; 30.912,35.3 30.912,36.525 ; 30.914,27.496 30.932,26.59
M1-Board Shape:
  lines w0.1: 0.001,50.3 0.001,1.143 1.139,0.005 41.852,0.005 43.002,1.145 43.001,39.986 43.001,50.35 ; 0.001,50.324 1.132,51.455 41.913,51.455 43.001,50.367
M4-Bottom Dimensions:
  lines w0.1: 2.335,-4.995 2.335,33.793 39.969,33.793 ; 36.625,-4.995 36.625,33.793
  lines w0.254: 2.399,-5.229 2.399,-4.721 ; 3.923,-5.483 2.399,-4.975 ; 3.923,-4.467 2.399,-4.975 ; 12.282,-4.975 2.399,-4.975 ; 26.807,-4.975 36.689,-4.975 ; 35.165,-5.483 36.689,-4.975 ; 35.165,-4.467 36.689,-4.975 ; 36.689,-5.229 36.689,-4.721
  text "34.29 (mm)" at 12.536,-5.889 h1.52
  text "CN1/CN2 spacing" at 12.49,-7.188 h0.81
M14-Top Assembly:
  lines w0.01: 14.4,55.45 19.9,55.45 ; 14,56.2 20.3,56.6 ; 14,56.2 14.4,56.6 ; 14,56.2 14.4,55.8 ; 14,56.2 14,59.4 ; 14,57 20.3,57.4 ; 14,57 14.4,56.6 ; 14,57 14.4,57.4 ; 14,57.8 20.3,58.2 ; 14,57.8 14.4,57.4 ; 14,57.8 14.4,58.2 ; 14,58.6 20.3,59 ; 14,58.6 14.4,58.2 ; 14,58.6 14.4,59 ; 14,59.4 14.4,59 ; 14,59.4 14.4,59.425 20.3,59.8 ; 14,59.4 14.4,59.8 ; 14.25,52.9 20.05,52.9 ; 14.25,52.9 12.35,52.9 12.35,46.5 13.45,46.5 13.45,51.25 20.85,51.25 20.85,46.5 21.95,46.5 21.95,52.9 20.05,52.9 ; 14.25,52.9 14.4,53.05 ; 14.4,53.05 19.9,53.05 ; 14.4,53.05 14.4,55.8 ; 14.4,55.8 14.4,59.8 ; 14.4,55.8 19.9,56.2 ; 14.4,56.6 19.9,57 ; 14.4,57.4 19.9,57.8 ; 14.4,58.2 19.9,58.6 ; 14.4,59 19.9,59.4 ; 14.4,59.8 19.9,60.2 ; 14.4,59.8 14.4,60.725 14.475,60.8 19.825,60.8 19.9,60.725 19.9,60.2 ; 19.9,53.05 19.9,56.2 ; 19.9,53.05 20.05,52.9 ; 19.9,56.2 19.9,60.2 ; 19.9,56.2 20.3,56.6 ; 19.9,57 20.3,57.4 ; 19.9,57 19.9,57 ; 19.9,57 20.3,56.6 ; 19.9,57.8 20.3,58.2 ; 19.9,57.8 20.3,57.4 ; 19.9,58.6 20.3,59 ; 19.9,58.6 20.3,58.2 ; 19.9,59.4 20.3,59.8 ; 19.9,59.4 20.3,59 ; 19.9,60.2 20.3,59.8 ; 20.3,56.6 20.3,59.8
M15-Bottom Assembly:
  text "C2" at 8.826,33.934 h0.8 r270
Drill Drawing:
  circle w0.254: c-15.118,80.172 r0.701
  lines w0.254: -15.819,76.317 -14.417,76.317 -14.417,77.718 -15.819,77.718 -15.819,76.317 ; -15.819,82.975 -15.468,82.975 -15.468,82.625 -14.767,82.625 -14.767,82.975 -14.417,82.975 -14.417,83.676 -14.767,83.676 -14.767,84.027 -15.468,84.027 -15.468,83.676 -15.819,83.676 -15.819,82.975
  lines w0.381: -17.09,75.37 126.325,75.37 ; -17.09,84.833 126.325,84.833 ; -8.983,72.216 -8.983,87.987 ; -1.565,72.216 -1.565,87.987 ; 12.35,72.216 12.35,87.987 ; 18.636,72.216 18.636,87.987 ; 27.787,72.216 27.787,87.987 ; 45.13,72.216 45.13,87.987 ; 52.628,72.216 52.628,87.987 ; 62.424,72.216 62.424,87.987 ; 85.354,72.216 85.354,87.987 ; 95.192,72.216 95.192,87.987 ; 110.491,72.216 110.491,87.987 ; -17.09,72.216 126.325,72.216 126.325,87.987 -17.09,87.987 -17.09,72.216
  text "Symbol" at -15.197,85.779 h1.83
  text "Count" at -8.037,85.779 h1.83
  text "Hole Size" at -0.618,85.779 h1.83
  text "Plated" at 13.296,85.779 h1.83
  text "Hole Type" at 19.582,85.779 h1.83
  text "Drill Layer Pair" at 28.733,85.779 h1.83
  text "Via/Pad" at 46.076,85.779 h1.83
  text "Pad Shape" at 53.575,85.779 h1.83
  text "Template" at 63.371,85.779 h1.83
  text "Description" at 86.3,85.779 h1.83
  text "Hole Tolerance (+)" at 96.138,85.779 h1.83
  text "Hole Tolerance (-)" at 111.437,85.779 h1.83
  text "2" at -8.037,82.625 h1.52
  text "1.000mm (39.37mil)" at -0.618,82.625 h1.52
  text "NPTH" at 13.296,82.625 h1.52
  text "Round" at 19.582,82.625 h1.52
  text "Top Layer - Bottom Layer" at 28.733,82.625 h1.52
  text "Pad" at 46.076,82.625 h1.52
  text "Rounded" at 53.575,82.625 h1.52
  text "c0hn100m110p0" at 63.371,82.625 h1.52
  text "287" at -8.037,79.471 h1.52
  text "0.300mm (11.81mil)" at -0.618,79.471 h1.52
  text "PTH" at 13.296,79.471 h1.52
  text "Round" at 19.582,79.471 h1.52
  text "Top Layer - Bottom Layer" at 28.733,79.471 h1.52
  text "Via" at 46.076,79.471 h1.52
  text "Rounded" at 53.575,79.471 h1.52
  text "v60h30m0mx0(Tol1-2)_564437741" at 63.371,79.471 h1.52
  text "0.010mm (0.39mil)" at 96.138,79.471 h1.52
  text "0.020mm (0.79mil)" at 111.437,79.471 h1.52
  text "469" at -8.037,76.317 h1.52
  text "0.300mm (11.81mil)" at -0.618,76.317 h1.52
  text "PTH" at 13.296,76.317 h1.52
  text "Round" at 19.582,76.317 h1.52
  text "Top Layer - Bottom Layer" at 28.733,76.317 h1.52
  text "Via" at 46.076,76.317 h1.52
  text "Rounded" at 53.575,76.317 h1.52
  text "(Mixed)" at 63.371,76.317 h1.52
  text "758 Total" at -8.037,73.162 h1.52

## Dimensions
17.15,62.475 to 43.001,50.35 on M2-Board Dimensions
17.15,50 to 0.001,50.3 on M2-Board Dimensions
0.001,-0.496 to 43.002,0 on M2-Board Dimensions
1.139,0.005 to 1.127,51.45 on M2-Board Dimensions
